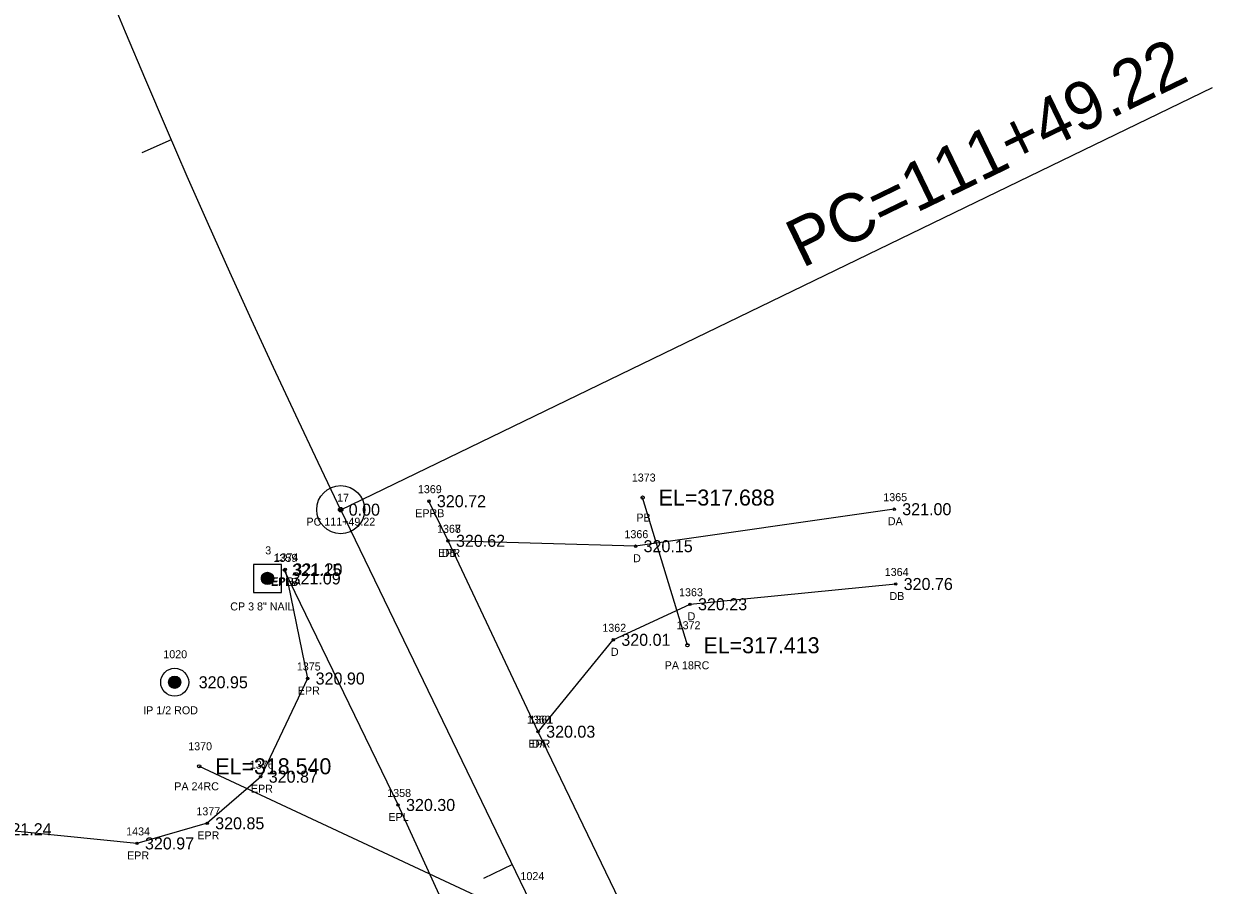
# Model space of a CAD drawing. Extents: x 1865045 to 1867370, y 910391 to 914218.
# Drawn here: x 1865995.4 to 1866144.3, y 911755.7 to 911863.2 of the extents above; entities that cross this region are included whole.
import ezdxf

# ---------------------------------------------------------------- set-up
doc = ezdxf.new("R2010")
doc.units = 0
for name, color, linetype in [('RD_EX_DR_Pipe', 7, 'Continuous'), ('RD_EX_DR_Pipe_txCode', 7, 'Continuous'), ('RD_EX_Driveway', 7, 'Continuous'), ('RD_EX_Driveway_txCode', 7, 'Continuous'), ('RD_EX_DV_Prop_txCode', 7, 'Continuous'), ('RD_EX_DV_PropPin', 7, 'Continuous'), ('RD_EX_Road', 7, 'Continuous'), ('RD_EX_Road_txCode', 7, 'Continuous'), ('RD_EX_TX_Driveway_ELEV', 7, 'Continuous'), ('RD_EX_TX_DV_Prop_ELEV', 7, 'Continuous'), ('RD_EX_TX_Road_ELEV', 7, 'Continuous'), ('RD_HC_Cl', 7, 'Continuous'), ('RD_HC_Data', 7, 'Continuous'), ('RD_HC_Data_Tic', 7, 'Continuous'), ('RD_HC_Survey', 7, 'Continuous'), ('RD_HC_Survey_ELEV', 7, 'Continuous'), ('RD_HC_Survey_txCode', 7, 'Continuous'), ('RD_HC_txCode', 7, 'Continuous'), ('RD_SMD_Locator', 7, 'Continuous'), ('RD_TX_Pipe_ElevEX', 7, 'Continuous')]:
    doc.layers.add(name, color=color, linetype=linetype)

msp = doc.modelspace()

# ---------------------------------------------------------------- linework, layer by layer
at = {"layer": 'RD_EX_DR_Pipe'}
for p, q in [((1866078.29, 911785.63), (1866072.69, 911804.07)), ((1866017.31, 911770.52), (1866089.93, 911736.64))]:
    msp.add_line(p, q, dxfattribs=at)
at = {"layer": 'RD_EX_Driveway'}
for points in [[(1866104.12, 911802.62), (1866071.81, 911798), (1866048.38, 911798.67)], [(1866059.64, 911774.84), (1866069.03, 911786.31), (1866078.61, 911790.75), (1866104.3, 911793.28)]]:
    msp.add_lwpolyline(points, dxfattribs=at)
at = {"layer": 'RD_EX_DV_PropPin'}
for p, q in [((1866013.51, 911780.81), (1866013.51, 911781.2)), ((1866013.54, 911780.71), (1866013.54, 911781.3)), ((1866013.58, 911780.64), (1866013.58, 911781.38)), ((1866013.61, 911780.58), (1866013.61, 911781.43)), ((1866013.65, 911780.53), (1866013.65, 911781.48)), ((1866013.68, 911780.49), (1866013.68, 911781.52)), ((1866013.72, 911780.46), (1866013.72, 911781.56)), ((1866013.75, 911780.42), (1866013.75, 911781.59)), ((1866013.79, 911780.4), (1866013.79, 911781.62)), ((1866013.82, 911780.37), (1866013.82, 911781.64)), ((1866013.86, 911780.35), (1866013.86, 911781.66)), ((1866013.89, 911780.33), (1866013.89, 911781.68)), ((1866013.93, 911780.31), (1866013.93, 911781.7)), ((1866013.96, 911780.3), (1866013.96, 911781.71)), ((1866014, 911780.29), (1866014, 911781.73)), ((1866014.03, 911780.27), (1866014.03, 911781.74)), ((1866014.07, 911780.27), (1866014.07, 911781.75)), ((1866014.1, 911780.26), (1866014.1, 911781.75)), ((1866014.14, 911780.25), (1866014.14, 911781.76)), ((1866014.17, 911780.25), (1866014.17, 911781.76)), ((1866014.21, 911780.25), (1866014.21, 911781.77)), ((1866014.24, 911780.25), (1866014.24, 911781.77)), ((1866014.28, 911780.25), (1866014.28, 911781.77)), ((1866014.31, 911780.25), (1866014.31, 911781.76)), ((1866014.35, 911780.25), (1866014.35, 911781.76)), ((1866014.38, 911780.26), (1866014.38, 911781.75)), ((1866014.42, 911780.27), (1866014.42, 911781.75)), ((1866014.45, 911780.27), (1866014.45, 911781.74)), ((1866014.49, 911780.29), (1866014.49, 911781.73)), ((1866014.52, 911780.3), (1866014.52, 911781.71)), ((1866014.56, 911780.31), (1866014.56, 911781.7)), ((1866014.59, 911780.33), (1866014.59, 911781.68)), ((1866014.63, 911780.35), (1866014.63, 911781.66)), ((1866014.66, 911780.37), (1866014.66, 911781.64)), ((1866014.7, 911780.4), (1866014.7, 911781.62)), ((1866014.73, 911780.42), (1866014.73, 911781.59)), ((1866014.77, 911780.46), (1866014.77, 911781.56)), ((1866014.8, 911780.49), (1866014.8, 911781.52)), ((1866014.84, 911780.53), (1866014.84, 911781.48)), ((1866014.87, 911780.58), (1866014.87, 911781.43)), ((1866014.91, 911780.64), (1866014.91, 911781.38)), ((1866014.94, 911780.71), (1866014.94, 911781.3)), ((1866014.98, 911780.81), (1866014.98, 911781.2))]:
    msp.add_line(p, q, dxfattribs=at)
for radius in [1.75, 0.761]:
    msp.add_circle((1866014.24, 911781.01), radius, dxfattribs=at)
at = {"layer": 'RD_EX_Road'}
for points in [[(1866367.09, 911115.22), (1866376.17, 911119.76), (1866330.4, 911213.7), (1866286.92, 911304.16), (1866242.4, 911396.3), (1866197.74, 911488.67), (1866154.31, 911579.91), (1866143.08, 911603.17), (1866108.16, 911674.25), (1866059.64, 911774.84), (1866048.38, 911798.67), (1866045.99, 911803.62)], [(1866028.06, 911795.11), (1866030.85, 911781.48), (1866024.99, 911769.22), (1866018.3, 911763.4), (1866009.53, 911760.89), (1865991.73, 911762.66)], [(1866367.09, 911115.22), (1866357.99, 911110.97), (1866313.12, 911203.44), (1866268.86, 911295.9), (1866224.24, 911388.66), (1866179.87, 911480.6), (1866149.84, 911543.41), (1866142.18, 911559.37), (1866135.93, 911572.05), (1866096.83, 911651.51), (1866089.65, 911665.46), (1866062.87, 911720.39), (1866042.14, 911765.69), (1866027.93, 911795.04)]]:
    msp.add_lwpolyline(points, dxfattribs=at)
at = {"layer": 'RD_HC_Cl'}
msp.add_line((1866280.52, 911295.32), (1866034.98, 911802.56), dxfattribs=at)
msp.add_arc((1867116.95, 912326.33), 1202.09, 166.19447, 205.83091, dxfattribs=at)
at = {"layer": 'RD_HC_Data'}
msp.add_line((1866034.98, 911802.56), (1866143.86, 911855.27), dxfattribs=at)
for radius in [3, 0.282]:
    msp.add_circle((1866034.98, 911802.56), radius, dxfattribs=at)
at = {"layer": 'RD_HC_Data_Tic'}
for p, q in [((1866013.82, 911848.72), (1866010.15, 911847.13)), ((1866056.42, 911758.25), (1866052.82, 911756.51))]:
    msp.add_line(p, q, dxfattribs=at)
at = {"layer": 'RD_HC_Survey'}
for p, q in [((1866025.21, 911793.53), (1866025.21, 911794.43)), ((1866025.24, 911793.5), (1866025.24, 911794.46)), ((1866025.26, 911793.47), (1866025.26, 911794.49)), ((1866025.29, 911793.44), (1866025.29, 911794.51)), ((1866025.31, 911793.42), (1866025.31, 911794.54)), ((1866025.34, 911793.39), (1866025.34, 911794.56)), ((1866025.36, 911793.37), (1866025.36, 911794.58)), ((1866025.39, 911793.35), (1866025.39, 911794.6)), ((1866025.41, 911793.34), (1866025.41, 911794.62)), ((1866025.44, 911793.32), (1866025.44, 911794.63)), ((1866025.46, 911793.31), (1866025.46, 911794.65)), ((1866025.48, 911793.29), (1866025.48, 911794.66)), ((1866025.51, 911793.28), (1866025.51, 911794.67)), ((1866025.53, 911793.27), (1866025.53, 911794.68)), ((1866025.56, 911793.26), (1866025.56, 911794.69)), ((1866025.58, 911793.25), (1866025.58, 911794.7)), ((1866025.61, 911793.24), (1866025.61, 911794.71)), ((1866025.63, 911793.24), (1866025.63, 911794.72)), ((1866025.66, 911793.23), (1866025.66, 911794.73)), ((1866025.68, 911793.22), (1866025.68, 911794.73)), ((1866025.71, 911793.22), (1866025.71, 911794.74)), ((1866025.73, 911793.21), (1866025.73, 911794.74)), ((1866025.76, 911793.21), (1866025.76, 911794.74)), ((1866025.78, 911793.21), (1866025.78, 911794.74)), ((1866025.81, 911793.21), (1866025.81, 911794.75)), ((1866025.83, 911793.21), (1866025.83, 911794.75)), ((1866025.86, 911793.21), (1866025.86, 911794.75)), ((1866025.88, 911793.21), (1866025.88, 911794.75)), ((1866025.91, 911793.21), (1866025.91, 911794.74)), ((1866025.93, 911793.21), (1866025.93, 911794.74)), ((1866025.96, 911793.22), (1866025.96, 911794.74)), ((1866025.98, 911793.22), (1866025.98, 911794.73)), ((1866026, 911793.23), (1866026, 911794.73)), ((1866026.03, 911793.23), (1866026.03, 911794.72)), ((1866026.05, 911793.24), (1866026.05, 911794.72)), ((1866026.08, 911793.25), (1866026.08, 911794.71)), ((1866026.1, 911793.26), (1866026.1, 911794.7)), ((1866026.13, 911793.26), (1866026.13, 911794.69)), ((1866026.15, 911793.28), (1866026.15, 911794.68)), ((1866026.18, 911793.29), (1866026.18, 911794.67)), ((1866026.2, 911793.3), (1866026.2, 911794.65)), ((1866026.23, 911793.31), (1866026.23, 911794.64)), ((1866026.25, 911793.33), (1866026.25, 911794.63)), ((1866026.28, 911793.35), (1866026.28, 911794.61)), ((1866026.3, 911793.36), (1866026.3, 911794.59)), ((1866026.33, 911793.38), (1866026.33, 911794.57)), ((1866026.35, 911793.4), (1866026.35, 911794.55)), ((1866026.38, 911793.43), (1866026.38, 911794.53)), ((1866026.4, 911793.45), (1866026.4, 911794.5)), ((1866026.43, 911793.48), (1866026.43, 911794.47)), ((1866026.45, 911793.51), (1866026.45, 911794.44)), ((1866026.47, 911793.55), (1866026.47, 911794.41)), ((1866025.09, 911793.8), (1866025.09, 911794.16)), ((1866025.11, 911793.72), (1866025.11, 911794.24)), ((1866025.14, 911793.66), (1866025.14, 911794.3)), ((1866025.16, 911793.61), (1866025.16, 911794.35)), ((1866025.19, 911793.56), (1866025.19, 911794.39)), ((1866026.5, 911793.59), (1866026.5, 911794.37)), ((1866026.52, 911793.63), (1866026.52, 911794.32)), ((1866026.55, 911793.68), (1866026.55, 911794.27)), ((1866026.57, 911793.75), (1866026.57, 911794.2)), ((1866026.6, 911793.87), (1866026.6, 911794.09))]:
    msp.add_line(p, q, dxfattribs=at)
msp.add_lwpolyline([(1866027.59, 911795.73), (1866024.09, 911795.73), (1866024.09, 911792.23), (1866027.59, 911792.23)], close=True, dxfattribs=at)
msp.add_circle((1866025.84, 911793.98), 0.769, dxfattribs=at)
at = {"layer": 'RD_SMD_Locator'}
for centre, radius in [((1866045.99, 911803.62), 0.15), ((1866072.69, 911804.07), 0.2), ((1866034.98, 911802.56), 0.15), ((1866104.12, 911802.62), 0.15), ((1866048.38, 911798.67), 0.15), ((1866048.38, 911798.67), 0.15), ((1866071.81, 911798), 0.15), ((1866027.93, 911795.04), 0.15), ((1866028.06, 911795.11), 0.15), ((1866025.84, 911793.98), 0.15), ((1866104.3, 911793.28), 0.15), ((1866078.61, 911790.75), 0.15), ((1866069.03, 911786.31), 0.15), ((1866078.29, 911785.63), 0.2), ((1866014.24, 911781.01), 0.15), ((1866030.85, 911781.48), 0.15), ((1866059.64, 911774.84), 0.15), ((1866059.64, 911774.84), 0.15), ((1866017.31, 911770.52), 0.2), ((1866024.99, 911769.22), 0.15), ((1866042.14, 911765.69), 0.15), ((1866018.3, 911763.4), 0.15), ((1866009.53, 911760.89), 0.15)]:
    msp.add_circle(centre, radius, dxfattribs=at)

# ---------------------------------------------------------------- texts
at = {"layer": 'RD_EX_DR_Pipe_txCode'}
for s, p in [('1373', (1866071.34, 911806.07)), ('PB', (1866071.91, 911801.07)), ('1372', (1866076.94, 911787.63)), ('PA 18RC', (1866075.45, 911782.63)), ('1370', (1866015.93, 911772.52)), ('PA 24RC', (1866014.19, 911767.52))]:
    msp.add_text(s, height=1, dxfattribs=at).set_placement(p)
at = {"layer": 'RD_EX_Driveway_txCode'}
for s, p in [('1365', (1866102.75, 911803.62)), ('1367', (1866047.01, 911799.67)), ('DA', (1866103.32, 911800.62)), ('1366', (1866070.42, 911799)), ('DB', (1866047.6, 911796.67)), ('D', (1866071.5, 911796)), ('1364', (1866102.93, 911794.28)), ('1363', (1866077.24, 911791.75)), ('DB', (1866103.52, 911791.28)), ('D', (1866078.31, 911788.75)), ('1362', (1866067.66, 911787.31)), ('D', (1866068.73, 911784.31)), ('1361', (1866058.55, 911775.84)), ('DA', (1866058.85, 911772.84))]:
    msp.add_text(s, height=1, dxfattribs=at).set_placement(p)
at = {"layer": 'RD_EX_DV_Prop_txCode'}
for s, p in [('1020', (1866012.82, 911784.01)), ('IP 1/2 ROD', (1866010.31, 911777.01)), ('1024', (1866057.43, 911756.31))]:
    msp.add_text(s, height=1, dxfattribs=at).set_placement(p)
at = {"layer": 'RD_EX_Road_txCode'}
for s, p in [('1369', (1866044.62, 911804.62)), ('EPRB', (1866044.29, 911801.62)), ('1368', (1866047.01, 911799.67)), ('EPR', (1866047.15, 911796.67)), ('1359', (1866026.58, 911796.04)), ('1374', (1866026.71, 911796.11)), ('EPLB', (1866026.25, 911793.04)), ('EPRA', (1866026.34, 911793.11)), ('1375', (1866029.5, 911782.48)), ('EPR', (1866029.62, 911779.48)), ('1360', (1866058.23, 911775.84)), ('EPR', (1866058.41, 911772.84)), ('1376', (1866023.62, 911770.22)), ('EPR', (1866023.76, 911767.22)), ('1358', (1866040.79, 911766.69)), ('1377', (1866016.95, 911764.4)), ('EPL', (1866040.93, 911763.69)), ('1434', (1866008.18, 911761.89)), ('EPR', (1866017.07, 911761.4)), ('EPR', (1866008.3, 911758.89))]:
    msp.add_text(s, height=1, dxfattribs=at).set_placement(p)
at = {"layer": 'RD_EX_TX_Driveway_ELEV'}
for s, p in [('321.00', (1866105.12, 911801.87)), ('320.62', (1866049.38, 911797.92)), ('320.15', (1866072.81, 911797.25)), ('320.76', (1866105.3, 911792.53)), ('320.23', (1866079.61, 911790)), ('320.01', (1866070.03, 911785.56)), ('320.03', (1866060.64, 911774.09))]:
    msp.add_text(s, height=1.5, dxfattribs=at).set_placement(p)
at = {"layer": 'RD_EX_TX_DV_Prop_ELEV'}
msp.add_text('320.95', height=1.5, dxfattribs=at).set_placement((1866017.24, 911780.26))
at = {"layer": 'RD_EX_TX_Road_ELEV'}
for s, p in [('320.72', (1866046.99, 911802.87)), ('320.62', (1866049.38, 911797.92)), ('321.15', (1866028.93, 911794.29)), ('321.20', (1866029.06, 911794.36)), ('320.90', (1866031.85, 911780.73)), ('320.03', (1866060.64, 911774.09)), ('320.87', (1866025.99, 911768.47)), ('320.30', (1866043.14, 911764.94)), ('321.24', (1865992.73, 911761.91)), ('320.85', (1866019.3, 911762.65)), ('320.97', (1866010.53, 911760.14))]:
    msp.add_text(s, height=1.5, dxfattribs=at).set_placement(p)
at = {"layer": 'RD_HC_Data'}
msp.add_text('PC=111+49.22', height=6, rotation=25.8309, dxfattribs=at).set_placement((1866092.61, 911832.68))
at = {"layer": 'RD_HC_Survey_ELEV'}
for s, p in [('0.00', (1866035.98, 911801.81)), ('321.09', (1866028.84, 911793.23))]:
    msp.add_text(s, height=1.5, dxfattribs=at).set_placement(p)
at = {"layer": 'RD_HC_Survey_txCode'}
for s, p in [('3', (1866025.55, 911796.98)), ('CP 3 8" NAIL', (1866021.18, 911789.98))]:
    msp.add_text(s, height=1, dxfattribs=at).set_placement(p)
at = {"layer": 'RD_HC_txCode'}
for s, p in [('17', (1866034.53, 911803.56)), ('PC 111+49.22', (1866030.7, 911800.56))]:
    msp.add_text(s, height=1, dxfattribs=at).set_placement(p)
at = {"layer": 'RD_TX_Pipe_ElevEX'}
for s, p in [('EL=317.688', (1866074.69, 911803.07)), ('EL=317.413', (1866080.29, 911784.63)), ('EL=318.540', (1866019.31, 911769.52))]:
    msp.add_text(s, height=2, dxfattribs=at).set_placement(p)

doc.saveas('drawing.dxf')
